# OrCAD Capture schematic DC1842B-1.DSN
size Custom
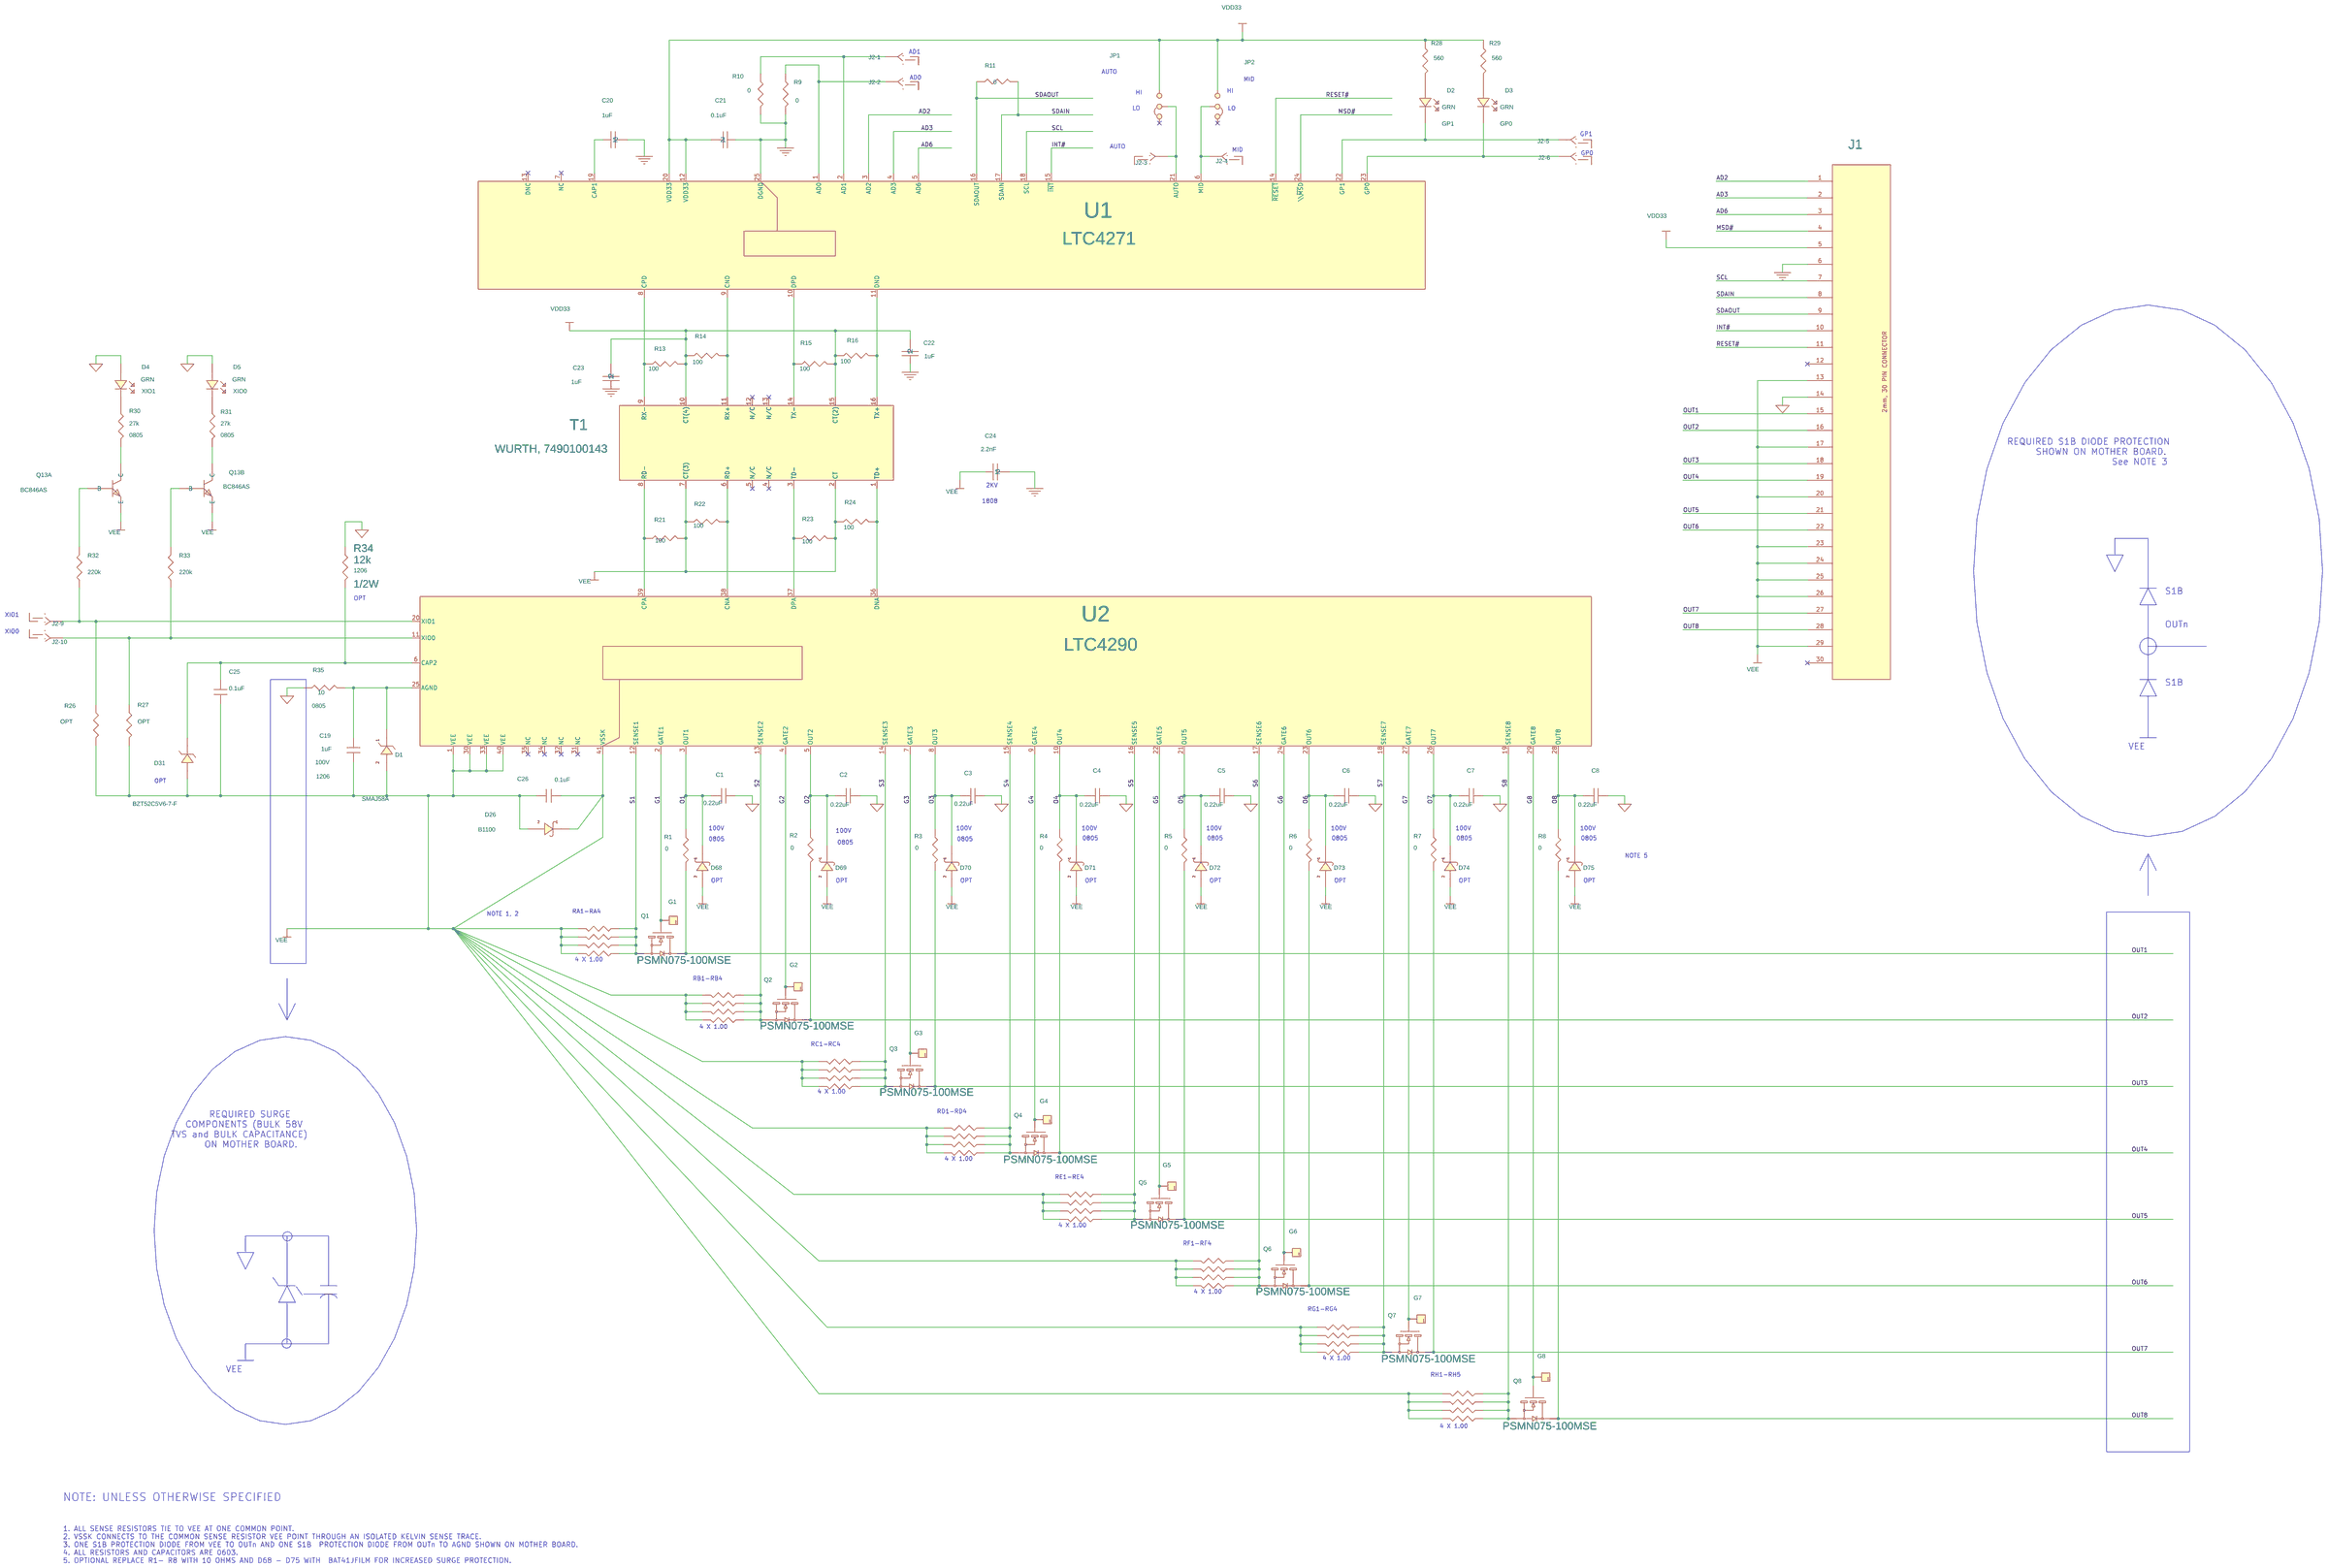
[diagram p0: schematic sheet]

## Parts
C1  0.22uF  [0805]
C2  0.22uF  [0805]
C3  0.22uF  [0805]
C4  0.22uF  [0805]
C5  0.22uF  [0805]
C6  0.22uF  [0805]
C7  0.22uF  [0805]
C8  0.22uF  [0805]
C19  1uF  [CAP1206]
C20  1uF  [CAP0603]
C21  0.1uF  [CAP0603]
C22  1uF  [CAP0603]
C23  1uF  [CAP0603]
C24  2.2nF  [CAP1808]
C25  0.1uF  [CAP0603]
C26  0.1uF  [CAP0603]
D1  SMAJ58A  [SMA]
D2  LED-LN  [0603-LED]
D3  LED-LN  [0603-LED]
D4  LED-LN  [0603-LED]
D5  LED-LN  [0603-LED]
D26  B1100  [SMA]
D31  BZT52C5V6-7-F  [SOD-123]
D68  BAT41JFILM  [SOD-323]
D69  BAT41JFILM  [SOD-323]
D70  BAT41JFILM  [SOD-323]
D71  BAT41JFILM  [SOD-323]
D72  BAT41JFILM  [SOD-323]
D73  BAT41JFILM  [SOD-323]
D74  BAT41JFILM  [SOD-323]
D75  BAT41JFILM  [SOD-323]
G1  PAD-SQ  [PAD-30SQ]
G2  PAD-SQ  [PAD-30SQ]
G3  PAD-SQ  [PAD-30SQ]
G4  PAD-SQ  [PAD-30SQ]
G5  PAD-SQ  [PAD-30SQ]
G6  PAD-SQ  [PAD-30SQ]
G7  PAD-SQ  [PAD-30SQ]
G8  PAD-SQ  [PAD-30SQ]
J1  30-Pin Right Angle Connector  [CON30/079-RT]
J2  CON-2X4-ED-2MM  [CON-2X5-ED-2MM]  (sections -1,-10,-2,-3,-4,-5,-6,-9)
JP1  JP3X1/079\NO\12  [JP3X1/079]
JP2  JP3X1/079\NO\12  [JP3X1/079]
Q1  PSMN075-100MSE  [POWER-33]
Q2  PSMN075-100MSE  [POWER-33]
Q3  PSMN075-100MSE  [POWER-33]
Q4  PSMN075-100MSE  [POWER-33]
Q5  PSMN075-100MSE  [POWER-33]
Q6  PSMN075-100MSE  [POWER-33]
Q7  PSMN075-100MSE  [POWER-33]
Q8  PSMN075-100MSE  [POWER-33]
Q13  BC846AS  [SOT-363]  (sections A,B)
R1  0  [0603]
R2  0  [0603]
R3  0  [0603]
R4  0  [0603]
R5  0  [0603]
R6  0  [0603]
R7  0  [0603]
R8  0  [0603]
R9  0  [RES0603]
R10  0  [RES0603]
R11  0  [RES0603]
R13  100  [RES0603]
R14  100  [RES0603]
R15  100  [RES0603]
R16  100  [RES0603]
R21  100  [RES0603]
R22  100  [RES0603]
R23  100  [RES0603]
R24  100  [RES0603]
R26  OPT  [RES0603]
R27  OPT  [RES0603]
R28  560  [0603]
R29  560  [0603]
R30  27k  [0805]
R31  27k  [0805]
R32  220k  [0603]
R33  220k  [0603]
R34  12k  [1206]
R35  10  [0805]
RA1  1.00  [RES0603]
RA2  1.00  [RES0603]
RA3  1.00  [RES0603]
RA4  1.00  [RES0603]
RB1  1.00  [RES0603]
RB2  1.00  [RES0603]
RB3  1.00  [RES0603]
RB4  1.00  [RES0603]
RC1  1.00  [RES0603]
RC2  1.00  [RES0603]
RC3  1.00  [RES0603]
RC4  1.00  [RES0603]
RD1  1.00  [RES0603]
RD2  1.00  [RES0603]
RD3  1.00  [RES0603]
RD4  1.00  [RES0603]
RE1  1.00  [RES0603]
RE2  1.00  [RES0603]
RE3  1.00  [RES0603]
RE4  1.00  [RES0603]
RF1  1.00  [RES0603]
RF2  1.00  [RES0603]
RF3  1.00  [RES0603]
RF4  1.00  [RES0603]
RG1  1.00  [RES0603]
RG2  1.00  [RES0603]
RG3  1.00  [RES0603]
RG4  1.00  [RES0603]
RH1  1.00  [RES0603]
RH2  1.00  [RES0603]
RH3  1.00  [RES0603]
RH4  1.00  [RES0603]
T1  WURTH, 7490100143  [TRANS-EPF8119S]
U1  Digital PSE Power Controller  [UF-24]
U2  8-Port PSE Power Controller  [UJ]

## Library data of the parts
C1-C8 = 06031C104MAT2A: CAP SMD 0805 0.22uF 10% 100V X7R; Part Number: AVX 08051C224KAT2A
C19 = CAP1206: 1ST PART FIELD: 100V; 2ND PART FIELD: 1206
C20 = C
C21 = C_1
C22 = C_4
C23 = C_3
C24 = C_2
C25 C26 = CAP0805
D1 = SMAJ5_0.0A-J170A: 4TH PART FIELD: Diodes Inc.,
D2 = LED-LTST-C190KRKT_0: 1ST PART FIELD: GRN; 3RD PART FIELD: GP1
D3 = LED-LTST-C190KRKT_0: 1ST PART FIELD: GRN; 3RD PART FIELD: GP0
D4 = LED-LTST-C190KRKT_0: 1ST PART FIELD: GRN; 3RD PART FIELD: XIO1
D5 = LED-LTST-C190KRKT_0: 1ST PART FIELD: GRN; 3RD PART FIELD: XIO0
D26 D68-D75 = diode_SCHOTTKY_BARRIER_0
D31 = DIODE-ZENER
G1-G8 = PAD-SQ: TEXT: GP2
J1 = LTC4258CGW_18: 4th Part Field: SAMTEC; 5th Part Field: 30 Pin Edge Connector; Part Number: TMM130-01-T-S-RA
J2 = CON-2X6-ED-2MM_0
JP1 JP2 = JP3X1_079_NO_12_1
Q1-Q8 = IRFM120A: XSTR, MOSFET, N-CHANNEL 100V
Q13 = BC846AS_0
R1-R8 = R
R9-R11 R13-R16 R21-R24 R26 R27 = AAC-0603
R28-R30 R32 R33 R35 = CRCW0603510RJNEA
R31 = CRCW0603510RJNEA: 1st Part Field: 0.125W
R34 = AAC-1206: 1ST PART FIELD: 1/2W; 4TH PART FIELD: VISHAY,
RA1-RA4 RB1-RB4 RC1-RC4 RD1-RD4 RE1-RE4 RF1-RF4 RG1-RG4 RH1-RH4 = AAC-0603: RES, 0603 1.00 OHMS 1% 1/10W; 2nd Part Field: 1%; Part Number: YAGEO RC0603FR-071RL
T1 = LTC6902_1: XFMR, GALVANIC GROUND ISOLATION, 1500V; Part Number: PAC ELEC. EPF8119S
U1 = LTC4258CGW_13: IC, LTC4271IUF, DIGITAL PSE CONTROLLER; 5th Part Field: LTC4271; Part Number: LINEAR TECH. LTC4271IUF
U2 = LTC4290xIUJ_3: 5th Part Field: LTC4290

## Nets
Agnd: C1.1 C2.1 C3.1 C4.1 C5.1 C6.1 C7.1 C8.1 D4.2 D5.2 J1.14 R34.1 R35.1
GND: C20.2 C21.1 C22.1 C23.1 C24.2 J1.6 R9.2 R10.2 U1.25(DGND)
VDD33: C21.2 C22.2 C23.2 J1.5 JP1.3 JP2.3 R13.2 R14.1 R15.2 R16.1 R28.1 R29.1 T1.10(CT(4)) T1.15(CT(2)) U1.12(VDD33) U1.20(VDD33)
VEE: C19.2 C24.1 C25.1 C26.1 C26.2 D1.2(ANODE) D26.1 D26.2 D31.2(ANODE) D68.2 D69.2 D70.2 D71.2 D72.2 D73.2 D74.2 D75.2 J1.13 J1.17 J1.20 J1.23 J1.24 J1.25 J1.26 J1.29 Q13.1(E) Q13.4(E) R21.2 R22.1 R23.2 R24.1 R26.2 R27.2 RA1.1 RA2.1 RA3.1 RA4.1 RB1.1 RB2.1 RB3.1 RB4.1 RC1.1 RC2.1 RC3.1 RC4.1 RD1.1 RD2.1 RD3.1 RD4.1 RE1.1 RE2.1 RE3.1 RE4.1 RF1.1 RF2.1 RF3.1 RF4.1 RG1.1 RG2.1 RG3.1 RG4.1 RH1.1 RH2.1 RH3.1 RH4.1 T1.2(CT) T1.7(CT(3)) U2.1(VEE) U2.30(VEE) U2.33(VEE) U2.40(VEE) U2.41(VSSK)
AD2: J1.1 U1.3(AD2)
AD3: J1.2 U1.4(AD3)
AD6: J1.3 U1.5(AD6)
G1: G1.1 Q1.4(G) U2.2(GATE1)
G2: G2.1 Q2.4(G) U2.4(GATE2)
G3: G3.1 Q3.4(G) U2.7(GATE3)
G4: G4.1 Q4.4(G) U2.9(GATE4)
G5: G5.1 Q5.4(G) U2.22(GATE5)
G6: G6.1 Q6.4(G) U2.24(GATE6)
G7: G7.1 Q7.4(G) U2.27(GATE7)
G8: G8.1 Q8.4(G) U2.29(GATE8)
INT#: J1.10 U1.15(~{INT})
MSD#: J1.4 U1.24(\\~{MS}D)
O1: C1.2 D68.1 R1.1 U2.3(OUT1)
O2: C2.2 D69.1 R2.1 U2.5(OUT2)
O3: C3.2 D70.1 R3.1 U2.8(OUT3)
O4: C4.2 D71.1 R4.1 U2.10(OUT4)
O5: C5.2 D72.1 R5.1 U2.21(OUT5)
O6: C6.2 D73.1 R6.1 U2.23(OUT6)
O7: C7.2 D74.1 R7.1 U2.26(OUT7)
O8: C8.2 D75.1 R8.1 U2.28(OUT8)
OUT1: J1.15 Q1.5(D) Q1.6(D) Q1.7(D) Q1.8(D) R1.2
OUT2: J1.16 Q2.5(D) Q2.6(D) Q2.7(D) Q2.8(D) R2.2
OUT3: J1.18 Q3.5(D) Q3.6(D) Q3.7(D) Q3.8(D) R3.2
OUT4: J1.19 Q4.5(D) Q4.6(D) Q4.7(D) Q4.8(D) R4.2
OUT5: J1.21 Q5.5(D) Q5.6(D) Q5.7(D) Q5.8(D) R5.2
OUT6: J1.22 Q6.5(D) Q6.6(D) Q6.7(D) Q6.8(D) R6.2
OUT7: J1.27 Q7.5(D) Q7.6(D) Q7.7(D) Q7.8(D) R7.2
OUT8: J1.28 Q8.5(D) Q8.6(D) Q8.7(D) Q8.8(D) R8.2
RESET#: J1.11 U1.14(~{RESET})
S1: Q1.1(S) Q1.2(S) Q1.3(S) RA1.2 RA2.2 RA3.2 RA4.2 U2.12(SENSE1)
S2: Q2.1(S) Q2.2(S) Q2.3(S) RB1.2 RB2.2 RB3.2 RB4.2 U2.13(SENSE2)
S3: Q3.1(S) Q3.2(S) Q3.3(S) RC1.2 RC2.2 RC3.2 RC4.2 U2.14(SENSE3)
S4: Q4.1(S) Q4.2(S) Q4.3(S) RD1.2 RD2.2 RD3.2 RD4.2 U2.15(SENSE4)
S5: Q5.1(S) Q5.2(S) Q5.3(S) RE1.2 RE2.2 RE3.2 RE4.2 U2.16(SENSE5)
S6: Q6.1(S) Q6.2(S) Q6.3(S) RF1.2 RF2.2 RF3.2 RF4.2 U2.17(SENSE6)
S7: Q7.1(S) Q7.2(S) Q7.3(S) RG1.2 RG2.2 RG3.2 RG4.2 U2.18(SENSE7)
S8: Q8.1(S) Q8.2(S) Q8.3(S) RH1.2 RH2.2 RH3.2 RH4.2 U2.19(SENSE8)
SCL: J1.7 U1.18(SCL)
SDAIN: J1.8 R11.2 U1.17(SDAIN)
SDAOUT: J1.9 R11.1 U1.16(SDAOUT)
N17148816: D2.1 J2.5(12) U1.22(GP1)
N17151573: D3.1 J2.6(12) U1.23(GP0)
N17170102: C20.1 U1.19(CAP1)
N17191472: J2.9(12) R26.1 R32.1 U2.20(XIO1)
N17369355: R22.2 T1.6(RD+) U2.38(CNA)
N17369357: R23.1 T1.3(TD-) U2.37(DPA)
N17369359: R14.2 T1.11(RX+) U1.9(CND)
N17369361: R15.1 T1.14(TX-) U1.10(DPD)
N17369368: R24.2 T1.1(TD+) U2.36(DNA)
N17369370: R21.1 T1.8(RD-) U2.39(CPA)
N17369378: R13.1 T1.9(RX-) U1.8(CPD)
N17369380: R16.2 T1.16(TX+) U1.11(DND)
N17405029: J2.4(12) JP2.2 U1.6(MID)
N17409737: J2.3(12) JP1.2 U1.21(AUTO)
N17474493: J2.2(12) R9.1 U1.1(AD0)
N17474495: J2.1(12) R10.1 U1.2(AD1)
N17545701: C19.1 D1.1(CATHODE) R35.2 U2.25(AGND)
N17550406: C25.2 D31.1(CATHODE) R34.2 U2.6(CAP2)
N17559160: J2.10(12) R27.1 R33.1 U2.11(XIO0)
N17725408: Q13.3(C) R31.2
N18332943: Q13.6(C) R30.2
N18771106: Q13.2(B) R32.2
N18771129: Q13.5(B) R33.2
N18778703: D2.2 R28.2
N18778704: D3.2 R29.2
N18778705: D4.1 R30.1
N18778706: D5.1 R31.1

Not connected (* = marked no-connect by the designer): J1 12* 30*; JP1 1*; JP2 1*; T1 4(N/C)* 5(N/C)* 12(N/C)* 13(N/C)*; U1 7(NC)* 13(DNC)*; U2 31(NC)* 32(NC)* 34(NC)* 35(NC)*

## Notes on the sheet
- AD1
- AD0
- AUTO
- MID
- HI
- HI
- LO
- LO
- GP1
- AUTO
- MID
- GP0
- REQUIRED S1B DIODE PROTECTION
        SHOWN ON MOTHER BOARD.
                        See NOTE 3
- 2KV
- 1808
- S1B
- OPT
- XIO1
- OUTn
- XIO0
- S1B
- VEE
- OPT
- 100V
- 100V
- 100V
- 100V
- 100V
- 100V
- 100V
- 100V
- 0805
- 0805
- 0805
- 0805
- 0805
- 0805
- 0805
- 0805
- NOTE 5
- OPT
- OPT
- OPT
- OPT
- OPT
- OPT
- OPT
- OPT
- NOTE 1, 2
- RA1-RA4
- 4 X 1.00
- RB1-RB4
- 4 X 1.00
- RC1-RC4
- 4 X 1.00
- REQUIRED SURGE
     COMPONENTS (BULK 58V
  TVS and BULK CAPACITANCE)
         ON MOTHER BOARD.
- RD1-RD4
- 4 X 1.00
- RE1-RE4
- 4 X 1.00
- RF1-RF4
- 4 X 1.00
- RG1-RG4
- 4 X 1.00
- VEE
- RH1-RH5
- 4 X 1.00
- NOTE: UNLESS OTHERWISE SPECIFIED
- 1. ALL SENSE RESISTORS TIE TO VEE AT ONE COMMON POINT.
  2. VSSK CONNECTS TO THE COMMON SENSE RESISTOR VEE POINT THROUGH AN ISOLATED KELVIN SENSE TRACE.
  3. ONE S1B PROTECTION DIODE FROM VEE TO OUTn AND ONE S1B  PROTECTION DIODE FROM OUTn TO AGND SHOWN ON MOTHER BOARD.
  4. ALL RESISTORS AND CAPACITORS ARE 0603.
  5. OPTIONAL REPLACE R1- R8 WITH 10 OHMS AND D68 - D75 WITH  BAT41JFILM FOR INCREASED SURGE PROTECTION.
